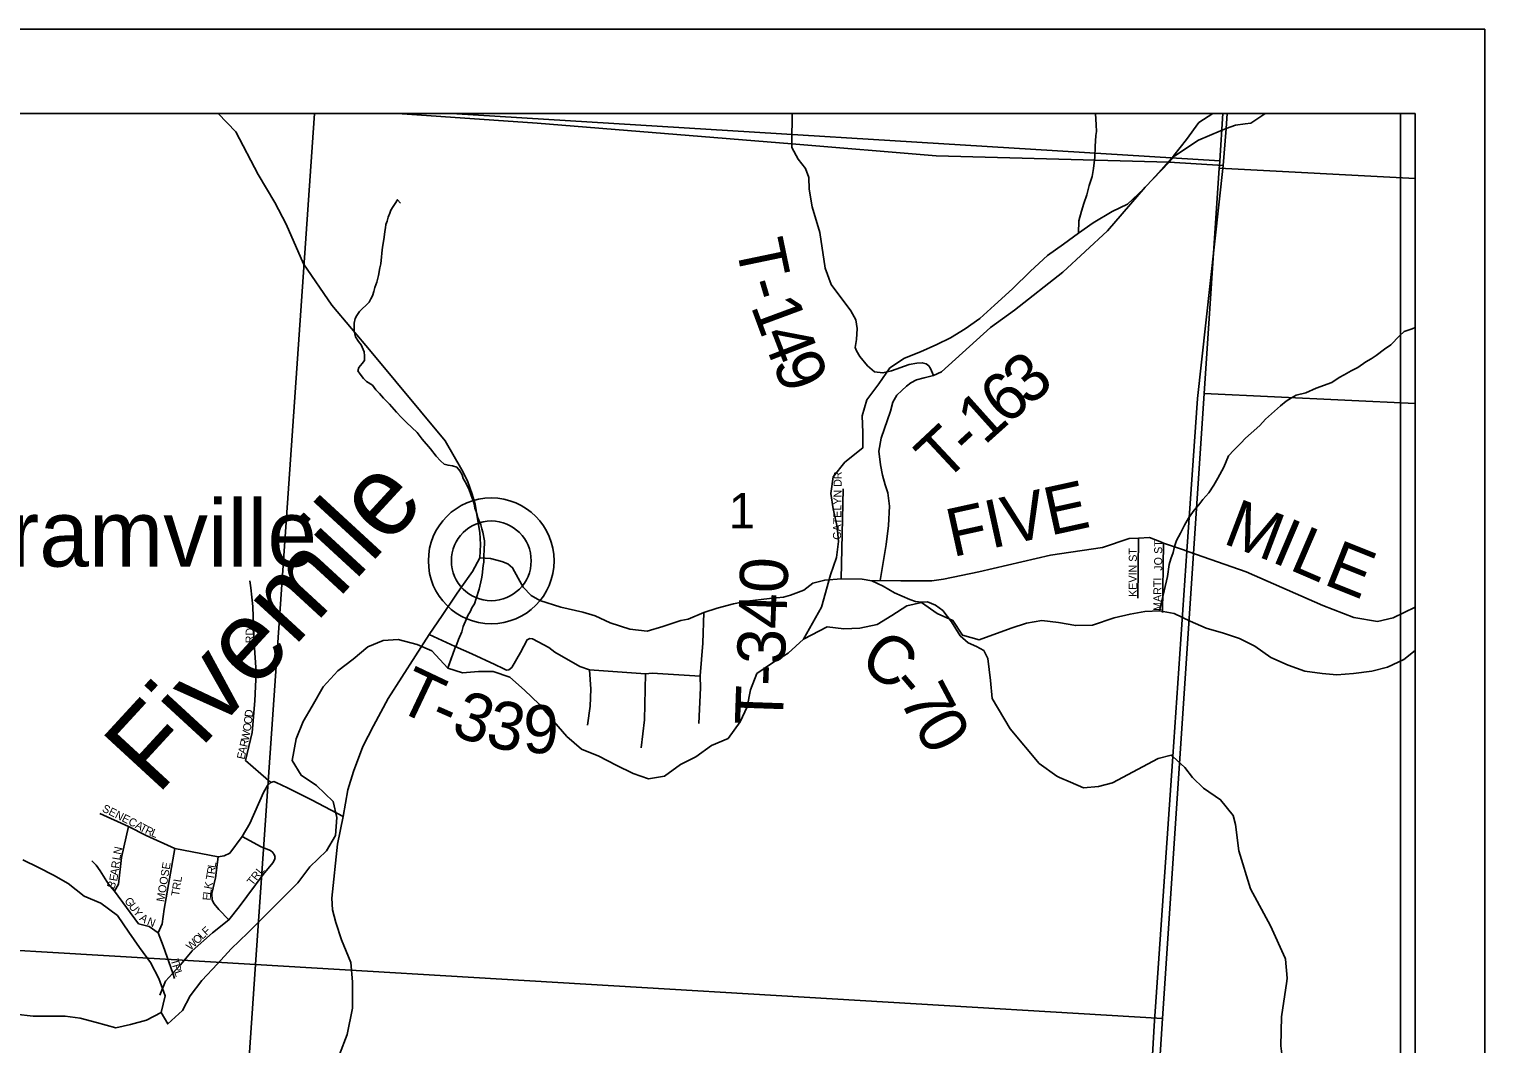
# Model space of a CAD drawing. Extents: x 0 to 34, y 0 to 22.
# Drawn here: x 7.778 to 9.5, y 19.8 to 21 of the extents above; entities that cross this region are included whole.
import ezdxf

# ---------------------------------------------------------------- set-up
doc = ezdxf.new("R2010")
doc.units = 0
for name, color, linetype in [('GM_X_County', 7, 'Continuous'), ('GM_X_County_Road', 7, 'Continuous'), ('GM_X_County_Road_Text', 7, 'Continuous'), ('GM_X_Minor_River', 7, 'Continuous'), ('GM_X_Minor_River_Text', 7, 'Continuous'), ('GM_X_Section', 7, 'Continuous'), ('GM_X_Section_Text', 7, 'Continuous'), ('GM_X_State_Route', 7, 'Continuous'), ('GM_X_Township', 7, 'Continuous'), ('GM_X_Township_Road', 7, 'Continuous'), ('GM_X_Township_Road_Text', 7, 'Continuous'), ('GM_X_Township_Subdivision', 7, 'Continuous'), ('GM_X_Township_Subdivision_Text', 7, 'Continuous'), ('GM_X_Unincorporated', 7, 'Continuous'), ('GM_X_Unincorporated_Location', 7, 'Continuous'), ('GM_X_Unincorporated_Text', 7, 'Continuous'), ('SH_Data', 7, 'Continuous')]:
    doc.layers.add(name, color=color, linetype=linetype)

msp = doc.modelspace()

# ---------------------------------------------------------------- linework, layer by layer
at = {"layer": 'GM_X_County'}
msp.add_lwpolyline([(9.4175, 16.6203), (9.4175, 20.9), (2.6175, 20.9), (2.6175, 15.1694)], dxfattribs=at)
at = {"layer": 'GM_X_County_Road'}
for points in [[(8.311, 20.3747), (8.3236, 20.3739), (8.337, 20.3704), (8.3441, 20.3676), (8.3496, 20.3628), (8.3562, 20.3507), (8.3622, 20.3398), (8.3715, 20.33), (8.3819, 20.3242), (8.4066, 20.3164), (8.4326, 20.3103), (8.4474, 20.3058), (8.465, 20.2978), (8.4882, 20.2902), (8.5088, 20.2877), (8.5273, 20.2932), (8.5487, 20.3003), (8.5573, 20.3021), (8.5758, 20.3099), (8.5915, 20.3149), (8.611, 20.3201), (8.627, 20.3235), (8.6535, 20.3264), (8.6703, 20.3281), (8.6783, 20.3306), (8.6942, 20.3365), (8.7048, 20.3445), (8.719, 20.3483), (8.7384, 20.3498), (8.7632, 20.3492), (8.7745, 20.3475), (8.7881, 20.3409), (8.8014, 20.333), (8.8195, 20.3252), (8.8264, 20.3228), (8.834, 20.3221), (8.8406, 20.3225), (8.85, 20.3185), (8.8588, 20.3122), (8.8691, 20.2989), (8.879, 20.2825), (8.8887, 20.2741), (8.8984, 20.2696), (8.9071, 20.265), (8.912, 20.2556), (8.915, 20.2293), (8.9172, 20.2082), (8.9384, 20.1722), (8.9726, 20.1313), (8.9934, 20.1162), (8.9969, 20.1147), (9.0096, 20.1092)], [(9.0096, 20.1092), (9.0252, 20.1026), (9.0427, 20.1041), (9.0593, 20.1083), (9.1134, 20.1372), (9.129, 20.1411), (9.1308, 20.1394), (9.1449, 20.1267), (9.154, 20.1149), (9.1669, 20.1021), (9.1873, 20.0884), (9.2021, 20.0699), (9.2048, 20.0592), (9.209, 20.0281), (9.2227, 19.983), (9.2462, 19.9391), (9.2636, 19.9009), (9.264, 19.9), (9.2659, 19.8772), (9.2655, 19.8738)], [(9.2655, 19.8738), (9.2595, 19.8317), (9.2584, 19.7972), (9.2607, 19.7816), (9.2657, 19.7699), (9.2956, 19.7282), (9.3191, 19.6941), (9.3275, 19.6895), (9.3589, 19.6862), (9.3945, 19.6855), (9.4131, 19.6757), (9.4175, 19.6725)]]:
    msp.add_lwpolyline(points, dxfattribs=at)
at = {"layer": 'GM_X_Minor_River'}
for points in [[(9.0191, 20.7586), (9.0195, 20.7734), (9.0227, 20.7848), (9.0255, 20.7939), (9.0291, 20.8041), (9.0319, 20.8151), (9.0355, 20.8256), (9.0368, 20.8351), (9.0385, 20.8484), (9.0391, 20.861), (9.0397, 20.8743), (9.0405, 20.8788), (9.0399, 20.8868), (9.0394, 20.9)], [(9.1616, 20.8897), (9.1781, 20.9)], [(9.1616, 20.8897), (9.147, 20.8695), (9.1319, 20.8505), (9.1137, 20.83), (9.0963, 20.811), (9.0773, 20.7928), (9.0592, 20.7844), (9.0365, 20.7708), (9.0191, 20.7586), (9.0016, 20.7457), (8.9827, 20.7321), (8.9623, 20.7138), (8.9411, 20.6926), (8.9199, 20.6736), (8.9025, 20.6577), (8.885, 20.6455), (8.8676, 20.6349), (8.8517, 20.6269)], [(8.2773, 20.2566), (8.2731, 20.2439), (8.2812, 20.2672), (8.2836, 20.2725), (8.2856, 20.2781), (8.2895, 20.2872), (8.2912, 20.2932), (8.2951, 20.3023), (8.2967, 20.3064), (8.2998, 20.3113), (8.3014, 20.3155), (8.3045, 20.3203), (8.3065, 20.3264), (8.3101, 20.3377), (8.313, 20.3498), (8.3138, 20.354), (8.3148, 20.3654), (8.3156, 20.3695), (8.3158, 20.3786), (8.3162, 20.3824), (8.3164, 20.3946), (8.3143, 20.4048), (8.3133, 20.4087), (8.3119, 20.4136), (8.3086, 20.4217), (8.3065, 20.4293), (8.305, 20.4335), (8.304, 20.4384), (8.3025, 20.443), (8.3007, 20.4484), (8.2978, 20.456), (8.2934, 20.4644), (8.2912, 20.4683), (8.2898, 20.4729), (8.2872, 20.4775), (8.2835, 20.4817), (8.2786, 20.4833), (8.2733, 20.4841), (8.2688, 20.4854), (8.2643, 20.4892), (8.2591, 20.495), (8.2525, 20.5035), (8.2428, 20.515), (8.2369, 20.5227), (8.2306, 20.5289), (8.2242, 20.5347), (8.2183, 20.5405), (8.2123, 20.5467), (8.2042, 20.5563), (8.1971, 20.5633), (8.1923, 20.5691), (8.1878, 20.5733), (8.1837, 20.5787), (8.1766, 20.583), (8.1733, 20.5869), (8.1692, 20.5919), (8.1666, 20.5957), (8.1678, 20.5999), (8.1717, 20.6044), (8.1744, 20.6081), (8.1745, 20.6134), (8.1742, 20.6184), (8.1705, 20.6264), (8.1672, 20.6306), (8.1639, 20.636), (8.1621, 20.6429), (8.1623, 20.652), (8.1635, 20.6576), (8.1655, 20.6614), (8.1686, 20.6659), (8.1721, 20.6697), (8.1759, 20.673), (8.1798, 20.6771), (8.1821, 20.6809), (8.1837, 20.6846), (8.1853, 20.6896), (8.1865, 20.6945), (8.1889, 20.7005), (8.1909, 20.7084), (8.1926, 20.7175), (8.1938, 20.7224), (8.1947, 20.7308), (8.1948, 20.7346), (8.1953, 20.7391), (8.1961, 20.7444), (8.1969, 20.7486), (8.1978, 20.7539), (8.1983, 20.7607), (8.1991, 20.7649), (8.1996, 20.7687), (8.2012, 20.7728), (8.2024, 20.7777), (8.2044, 20.7823), (8.2056, 20.786), (8.2083, 20.7902), (8.2106, 20.7939), (8.2133, 20.7981), (8.2171, 20.7942)], [(9.1152, 20.3122), (9.1151, 20.3119), (9.1246, 20.3524), (9.1264, 20.3668), (9.1284, 20.3732), (9.1311, 20.3808), (9.1328, 20.388), (9.1352, 20.3952), (9.1399, 20.4039), (9.1446, 20.4133), (9.1493, 20.4216), (9.1559, 20.431), (9.1617, 20.4374), (9.1663, 20.4434), (9.1733, 20.4513), (9.1795, 20.4607), (9.1842, 20.469), (9.1912, 20.4818), (9.1968, 20.4954), (9.2029, 20.5018), (9.2114, 20.5104), (9.2168, 20.516), (9.2234, 20.522), (9.2338, 20.531), (9.2404, 20.5388), (9.2477, 20.5448), (9.2581, 20.5542), (9.265, 20.5598), (9.2711, 20.5638), (9.2769, 20.5668), (9.2883, 20.5697), (9.3002, 20.5752), (9.3189, 20.5821), (9.3274, 20.5877), (9.3335, 20.591), (9.3419, 20.5958), (9.3496, 20.5999), (9.3592, 20.6066), (9.3653, 20.6099), (9.3715, 20.614), (9.3811, 20.6215), (9.3888, 20.6267), (9.3988, 20.6372), (9.4046, 20.6424), (9.4141, 20.6453), (9.4175, 20.6469)], [(8.8517, 20.6269), (8.8323, 20.6183), (8.8134, 20.6107), (8.796, 20.5993), (8.7831, 20.5804), (8.7687, 20.5614), (8.7633, 20.5425), (8.764, 20.5227), (8.764, 20.5045), (8.7428, 20.4879), (8.7291, 20.4704), (8.7261, 20.4507), (8.7291, 20.4325), (8.7336, 20.4112), (8.7351, 20.3938), (8.7328, 20.3748), (8.7259, 20.3544), (8.7153, 20.3164), (8.694, 20.2785), (8.6758, 20.2618), (8.6584, 20.2512), (8.6387, 20.2376), (8.6311, 20.2186), (8.6273, 20.1982), (8.6189, 20.1807), (8.6045, 20.161), (8.5848, 20.1527), (8.5666, 20.139), (8.5484, 20.13), (8.5295, 20.1163), (8.5105, 20.1133), (8.4924, 20.1194), (8.472, 20.1293), (8.4515, 20.1399), (8.4311, 20.1482), (8.4137, 20.1634), (8.3986, 20.1809), (8.3812, 20.2014), (8.3638, 20.2181), (8.3465, 20.2333), (8.3268, 20.2401), (8.3094, 20.2401), (8.2905, 20.2386), (8.2731, 20.2439), (8.2542, 20.2644), (8.2368, 20.272), (8.2141, 20.2781), (8.1966, 20.2766), (8.1785, 20.2691), (8.161, 20.2547), (8.1428, 20.241), (8.1254, 20.2221), (8.1125, 20.1993), (8.1019, 20.1811), (8.0935, 20.1606), (8.0889, 20.1348), (8.0995, 20.1174), (8.1176, 20.1052), (8.1373, 20.0863), (8.1418, 20.0673), (8.1403, 20.0461), (8.1296, 20.0279), (8.1099, 20.0089), (8.0955, 19.99), (8.0364, 19.9308), (8.0166, 19.9119), (8.0007, 19.8944), (7.9818, 19.8747), (7.9681, 19.8565), (7.959, 19.8391), (7.9416, 19.8232), (7.934, 19.8368)], [(8.8521, 20.3087), (8.8334, 20.3217), (8.8159, 20.3179), (8.7985, 20.3065), (8.7811, 20.2959), (8.7606, 20.2914), (8.7417, 20.2906), (8.722, 20.2929), (8.694, 20.2785)], [(8.8521, 20.3087), (8.8706, 20.3004), (8.8819, 20.2829), (8.9016, 20.2776), (8.9395, 20.2913), (8.9576, 20.2974), (8.9758, 20.3004), (8.9955, 20.2982), (9.0159, 20.2944), (9.0356, 20.2951), (9.0613, 20.3035), (9.0803, 20.3081), (9.0977, 20.3111), (9.1151, 20.3119), (9.1325, 20.3089), (9.1514, 20.2998), (9.1703, 20.2914), (9.1908, 20.2854), (9.2097, 20.2793), (9.2279, 20.2702), (9.2468, 20.2566), (9.2672, 20.2475), (9.2869, 20.2407), (9.3073, 20.2376), (9.3248, 20.2361), (9.3444, 20.2377), (9.3664, 20.2407), (9.3846, 20.2453), (9.4042, 20.2544), (9.4175, 20.2648)], [(7.77, 20.0175), (7.7889, 20.0084), (7.8063, 19.9993), (7.8237, 19.9894), (7.8426, 19.9742), (7.8623, 19.9659), (7.882, 19.9514), (7.8956, 19.9317), (7.9084, 19.9135), (7.9212, 19.896), (7.931, 19.8771), (7.9386, 19.8566), (7.934, 19.8368), (7.9166, 19.8278), (7.8976, 19.8225), (7.8802, 19.8187), (7.8575, 19.8248), (7.8379, 19.8301), (7.8204, 19.8324), (7.7826, 19.8324), (7.7614, 19.8347)]]:
    msp.add_lwpolyline(points, dxfattribs=at)
at = {"layer": 'GM_X_Section'}
for p, q in [((8.1151, 20.9), (7.0384, 20.9)), ((8.2775, 20.9), (8.1151, 20.9)), ((9.19, 20.9), (8.2775, 20.9)), ((9.4175, 20.557), (9.4175, 20.8231)), ((9.4175, 19.5279), (9.4175, 20.557))]:
    msp.add_line(p, q, dxfattribs=at)
for points in [[(7.0384, 20.9), (6.9795, 19.9566), (8.0453, 19.8934), (8.1151, 20.9)], [(8.1151, 20.9), (8.0453, 19.8934), (9.1186, 19.8297), (9.1679, 20.569), (9.1857, 20.8357), (9.1859, 20.8384), (9.1863, 20.8441), (8.2775, 20.9)], [(8.2775, 20.9), (9.1863, 20.8441), (9.19, 20.9)], [(9.19, 20.9), (9.1863, 20.8441), (9.1859, 20.8384), (9.1857, 20.8357), (9.4175, 20.8231)], [(9.4175, 20.8231), (9.4175, 20.9), (9.19, 20.9)], [(9.4175, 20.8231), (9.1857, 20.8357), (9.1679, 20.569), (9.4175, 20.557)], [(9.4175, 20.557), (9.1679, 20.569), (9.1186, 19.8297), (9.0999, 19.5424), (9.4175, 19.5279)]]:
    msp.add_lwpolyline(points, dxfattribs=at)
for points in [[(6.9795, 19.9566), (8.0453, 19.8934), (7.9764, 18.8836), (6.9173, 18.9472)], [(8.0453, 19.8934), (9.1186, 19.8297), (9.0999, 19.5424), (9.0522, 18.819), (7.9764, 18.8836)]]:
    msp.add_lwpolyline(points, close=True, dxfattribs=at)
at = {"layer": 'GM_X_State_Route'}
for points in [[(8.2878, 20.3379), (8.3024, 20.3583), (8.311, 20.3747), (8.3118, 20.3903), (8.311, 20.4044), (8.3082, 20.4208), (8.3053, 20.4379), (8.3018, 20.45), (8.2962, 20.4656), (8.2897, 20.4788), (8.27, 20.5131), (8.1825, 20.6182), (8.1358, 20.6736), (8.1023, 20.7224), (8.0816, 20.7691), (8.0684, 20.7951), (8.0487, 20.828), (8.0222, 20.8786), (8.0013, 20.9)], [(8.1447, 19.7869), (8.1541, 19.8107), (8.1601, 19.842), (8.1601, 19.8729), (8.1581, 19.8958), (8.1471, 19.9227), (8.1406, 19.9432), (8.1366, 19.9581), (8.1357, 19.9721), (8.1426, 20.0358), (8.1491, 20.0687), (8.1546, 20.1001), (8.1615, 20.122), (8.1725, 20.1514), (8.185, 20.1758), (8.2024, 20.2082), (8.2509, 20.2838), (8.2664, 20.3063), (8.2825, 20.3305), (8.2878, 20.3379)]]:
    msp.add_lwpolyline(points, dxfattribs=at)
at = {"layer": 'GM_X_Township'}
for p, q in [((8.2133, 20.9), (2.7154, 20.9)), ((9.195, 20.9), (8.2133, 20.9))]:
    msp.add_line(p, q, dxfattribs=at)
for points in [[(9.0224, 18.4988), (9.0811, 19.1844), (9.0872, 19.4578), (9.0922, 19.532), (9.1089, 19.821), (9.1308, 20.1394), (9.1474, 20.3825), (9.1598, 20.5629), (9.1905, 20.8388), (9.1263, 20.8428), (8.8507, 20.8503), (8.6801, 20.8642), (8.3786, 20.8887), (8.2133, 20.9)], [(8.2133, 20.9), (8.3786, 20.8887), (8.6801, 20.8642), (8.8507, 20.8503), (9.1263, 20.8428), (9.1905, 20.8388), (9.1939, 20.8823), (9.195, 20.9)], [(9.195, 20.9), (9.1939, 20.8823), (9.1905, 20.8388), (9.1598, 20.5629), (9.1474, 20.3825), (9.1308, 20.1394), (9.1089, 19.821), (9.0922, 19.532), (9.0872, 19.4578), (9.0811, 19.1844), (9.0224, 18.4988)], [(9.4175, 16.6203), (9.4175, 20.9), (9.195, 20.9)]]:
    msp.add_lwpolyline(points, dxfattribs=at)
at = {"layer": 'GM_X_Township_Road'}
for points in [[(8.8477, 20.5904), (8.844, 20.5985), (8.8421, 20.6016), (8.839, 20.6039), (8.8344, 20.6053), (8.828, 20.605), (8.8189, 20.6033), (8.7978, 20.5957), (8.7877, 20.5933), (8.7779, 20.5947), (8.7696, 20.6016), (8.7603, 20.6129), (8.7567, 20.6194), (8.755, 20.6234), (8.7564, 20.6327), (8.7572, 20.6457), (8.7559, 20.6562), (8.7497, 20.6668), (8.7265, 20.6981), (8.7193, 20.7172), (8.7131, 20.7596), (8.7039, 20.7896), (8.7006, 20.8108), (8.7002, 20.8246), (8.6962, 20.8353), (8.6875, 20.8461), (8.6802, 20.8599), (8.6801, 20.8642), (8.68, 20.8684), (8.6804, 20.8977), (8.6805, 20.9)], [(9.1872, 20.8795), (9.1939, 20.8823), (9.2048, 20.8864), (9.2163, 20.8878), (9.223, 20.8886), (9.2396, 20.8999)], [(9.2396, 20.8999), (9.2398, 20.9)], [(8.7745, 20.3475), (8.7847, 20.3478), (8.7917, 20.3905), (8.7942, 20.4128), (8.7956, 20.4357), (8.7935, 20.4515), (8.7906, 20.4608), (8.7873, 20.4723), (8.7848, 20.4847), (8.7829, 20.5008), (8.7857, 20.5163), (8.7966, 20.5482), (8.7997, 20.5586), (8.8043, 20.567), (8.8102, 20.5724), (8.8156, 20.5778), (8.8207, 20.5814), (8.8277, 20.585), (8.8367, 20.5874), (8.8477, 20.5904), (8.8572, 20.5947), (8.915, 20.6472), (8.9433, 20.6677), (9.0008, 20.7126), (9.0534, 20.7613), (9.098, 20.8129), (9.1263, 20.8428), (9.1332, 20.8502), (9.1612, 20.8685), (9.1872, 20.8795)], [(9.1496, 20.3818), (9.1474, 20.3825), (9.1445, 20.3836), (9.1198, 20.3921), (9.1174, 20.393), (9.103, 20.3986), (9.0902, 20.398), (9.0791, 20.3975), (9.0477, 20.3868), (8.986, 20.3776), (8.9011, 20.3581), (8.8594, 20.3494), (8.8455, 20.3475), (8.8089, 20.3472), (8.7847, 20.3478)], [(9.4175, 20.3161), (9.3913, 20.3035), (9.3731, 20.2993), (9.3451, 20.3038), (9.3083, 20.3182), (9.2174, 20.3582), (9.1496, 20.3818)], [(8.5714, 20.235), (8.5747, 20.2735), (8.5758, 20.3099)], [(8.2509, 20.2838), (8.2817, 20.2697), (8.3016, 20.2611), (8.3286, 20.2483), (8.3383, 20.2435), (8.3426, 20.2417), (8.3451, 20.2422), (8.3488, 20.2449), (8.3589, 20.2626), (8.3669, 20.2777), (8.3699, 20.2791), (8.373, 20.2786), (8.38, 20.2751), (8.3924, 20.2684), (8.3997, 20.2631), (8.4292, 20.2462), (8.4408, 20.2421), (8.5068, 20.2373), (8.5149, 20.2382), (8.5714, 20.2346)], [(8.4383, 20.1765), (8.4413, 20.1992), (8.4424, 20.2194), (8.4408, 20.2421)], [(8.5017, 20.1498), (8.5058, 20.1831), (8.5068, 20.2373)], [(8.5698, 20.1787), (8.5719, 20.2208), (8.5714, 20.2346), (8.5714, 20.235)]]:
    msp.add_lwpolyline(points, dxfattribs=at)
at = {"layer": 'GM_X_Township_Subdivision'}
for points in [[(8.7384, 20.3498), (8.7409, 20.4561)], [(9.0892, 20.327), (9.0902, 20.398)], [(9.1185, 20.3098), (9.1198, 20.3921)], [(8.0636, 20.109), (8.0519, 20.1192), (8.0337, 20.135), (8.0414, 20.168), (8.0446, 20.2054), (8.0464, 20.2394), (8.044, 20.2738), (8.0429, 20.3049), (8.0425, 20.3172), (8.0398, 20.3392), (8.0388, 20.3474)], [(7.8613, 20.0722), (7.8951, 20.0567), (7.916, 20.0463), (7.9499, 20.0308), (8.0012, 20.0209), (8.0082, 20.0219), (8.0151, 20.0254), (8.0296, 20.0448), (8.0386, 20.0602), (8.055, 20.0971), (8.0595, 20.1052), (8.0636, 20.109), (8.0673, 20.1098), (8.0699, 20.109), (8.0834, 20.1026), (8.1127, 20.0881), (8.1491, 20.0687)], [(7.8787, 19.9801), (7.8833, 19.9885), (7.8871, 20.0202), (7.8951, 20.0567)], [(7.9323, 19.8574), (7.9388, 19.8738), (7.9476, 19.8831), (7.9569, 19.8931), (7.9707, 19.9095), (7.9945, 19.931), (8.0141, 19.9462), (8.0261, 19.9616), (8.0546, 19.9999), (8.0659, 20.0139), (8.068, 20.0172), (8.0687, 20.0199), (8.0679, 20.0229), (8.0659, 20.0259), (8.0634, 20.0283), (8.052, 20.0328), (8.0296, 20.0448)], [(7.852, 20.0163), (7.857, 20.0109), (7.8615, 20.0042), (7.8716, 19.9887), (7.8787, 19.9801), (7.9072, 19.9418), (7.9197, 19.9385), (7.9304, 19.9308), (7.9363, 19.9156), (7.9476, 19.8831), (7.9497, 19.8769)], [(7.9304, 19.9308), (7.9349, 19.9415), (7.9375, 19.959), (7.9499, 20.0308)], [(8.0141, 19.9462), (8.0022, 19.9586), (7.9967, 19.9651), (7.9942, 19.9696), (7.9937, 19.9775), (7.9982, 19.996), (8.0012, 20.0209)]]:
    msp.add_lwpolyline(points, dxfattribs=at)
at = {"layer": 'GM_X_Unincorporated'}
for radius in [0.0744, 0.0472]:
    msp.add_circle((8.3244, 20.371), radius, dxfattribs=at)
at = {"layer": 'GM_X_Unincorporated_Location'}
msp.add_line((8.3244, 20.371), (8.3244, 20.371), dxfattribs=at)
at = {"layer": 'SH_Data'}
for p, q in [((2.5, 21), (9.5, 21)), ((9.5, 21), (9.5, 14)), ((2.6, 20.9), (9.4, 20.9)), ((9.4, 20.9), (9.4, 14.1))]:
    msp.add_line(p, q, dxfattribs=at)

# ---------------------------------------------------------------- texts
at = {"layer": 'GM_X_County_Road_Text'}
for s, rotation, p in [('C', 326.0539, (8.7574, 20.2462)), ('-', 310.1911, (8.793, 20.2229)), ('7', 297.9592, (8.8063, 20.2077)), ('0', 299.69, (8.8236, 20.1751))]:
    msp.add_text(s, height=0.0568, rotation=rotation, dxfattribs=at).set_placement(p)
at = {"layer": 'GM_X_Minor_River_Text'}
msp.add_text('Fivemile', height=0.09467, rotation=47.377, dxfattribs=at).set_placement((7.9292, 20.0928))
at = {"layer": 'GM_X_Section_Text'}
msp.add_text('1', height=0.0419, rotation=0, dxfattribs=at).set_placement((8.6054, 20.4093))
at = {"layer": 'GM_X_Township_Road_Text'}
for s, height, rotation, p in [('T', 0.0568, 281.7651, (8.6132, 20.7454)), ('-', 0.0568, 286.4334, (8.6231, 20.6989)), ('1', 0.0568, 290.322, (8.631, 20.6725)), ('4', 0.0568, 291.094, (8.6434, 20.6389)), ('9', 0.0568, 292.2156, (8.6565, 20.6051)), ('3', 0.0568, 40.1304, (8.9601, 20.5527)), ('6', 0.0568, 40.5235, (8.9336, 20.53)), ('1', 0.0568, 41.9129, (8.9078, 20.5069)), ('T', 0.0568, 43.0617, (8.8598, 20.4623)), ('-', 0.0568, 42.7128, (8.8908, 20.4912)), ('FIVE', 0.05682, 12.395, (8.8702, 20.3753)), ('M', 0.0568, 339.1674, (9.1886, 20.3922)), ('I', 0.0568, 336.9454, (9.2457, 20.3705)), ('L', 0.0568, 336.6842, (9.2671, 20.3613)), ('E', 0.0568, 338.2097, (9.3076, 20.3439)), ('T-340', 0.05682, 88.0354, (8.6693, 20.1759)), ('T', 0.0568, 334.6492, (8.2092, 20.1961)), ('3', 0.0568, 340.9315, (8.2752, 20.1659)), ('3', 0.0568, 348.4557, (8.3161, 20.1523)), ('-', 0.0568, 336.1219, (8.249, 20.1772)), ('9', 0.0568, 358.5496, (8.3613, 20.144))]:
    msp.add_text(s, height=height, rotation=rotation, dxfattribs=at).set_placement(p)
at = {"layer": 'GM_X_Township_Subdivision_Text'}
for s, rotation, p in [('GATELYN DR', 89.3493, (8.7382, 20.3959)), ('ST', 90, (9.1182, 20.3793)), ('KEVIN ST', 90, (9.0882, 20.3284)), ('JO', 90, (9.1182, 20.3593)), ('MARTI', 90, (9.1173, 20.3118)), ('RD', 90, (8.0432, 20.2734)), ('O', 83.2937, (8.0409, 20.1774)), ('D', 83.2965, (8.0418, 20.1856)), ('W', 77.9055, (8.0373, 20.1575)), ('O', 82.2642, (8.0397, 20.1689)), ('R', 77.3671, (8.0357, 20.1501)), ('E', 77.3586, (8.0324, 20.1355)), ('A', 77.3781, (8.0338, 20.142)), ('SENECA', 333.4359, (7.8632, 20.075)), ('T', 331.6141, (7.9075, 20.0525)), ('R', 335.2811, (7.9139, 20.049)), ('L', 338.0885, (7.9212, 20.0457)), ('N', 78.1344, (7.8863, 20.0229)), ('R', 82.4495, (7.8839, 20.0066)), ('L', 80.5034, (7.8852, 20.0164)), ('MOOSE', 80.534, (7.9374, 19.9671)), ('E', 80.7857, (7.8817, 19.9915)), ('A', 82.489, (7.8828, 19.9983)), ('TRL', 80.9147, (7.9549, 19.9737)), ('T', 79.4004, (7.9958, 19.9929)), ('R', 81.3744, (7.9971, 19.9998)), ('L', 81.8755, (7.9982, 20.0073)), ('TRL', 51.3355, (8.0419, 19.9862)), ('B', 64.7627, (7.8777, 19.9819)), ('L', 82.0515, (7.9927, 19.9756)), ('K', 78.4698, (7.9936, 19.982)), ('G', 307.7568, (7.8898, 19.9686)), ('U', 307.7786, (7.8949, 19.962)), ('E', 87.9779, (7.9925, 19.9692)), ('Y', 307.7552, (7.9, 19.9554)), ('A', 325.7324, (7.9074, 19.9466)), ('N', 338.8656, (7.9164, 19.9408)), ('O', 42.8783, (7.9765, 19.917)), ('L', 42.8781, (7.9826, 19.9227)), ('F', 42.8847, (7.9875, 19.9272)), ('W', 43.1286, (7.9686, 19.9096)), ('T', 285.9135, (7.945, 19.8989)), ('R', 285.9398, (7.9468, 19.8925)), ('L', 289.1571, (7.9491, 19.8847))]:
    msp.add_text(s, height=0.00947, rotation=rotation, dxfattribs=at).set_placement(p)
at = {"layer": 'GM_X_Unincorporated_Text'}
msp.add_text('Bartramville', height=0.078977, rotation=0, dxfattribs=at).set_placement((7.5608, 20.3642))

doc.saveas('drawing.dxf')
